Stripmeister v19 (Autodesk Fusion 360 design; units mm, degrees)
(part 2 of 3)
sketch "Sketch4" plane through (0, 0, 0) normal (0, 1, 0) x axis (1, 0, 0)
  line L1 (15.875, -65.6907) -> (15.875, -73.6282)
  line L2 (-15.875, -73.6282) -> (-15.875, -65.6907)
  line L3 (15.875, -73.6282) -> (-15.875, -73.6282)
  line L4 (15.875, -65.6907) -> (15.875, -73.6282)
  line L5 (-15.875, -65.6907) -> (15.875, -65.6907)
  line L6 (-15.875, -73.6282) -> (-15.875, -65.6907)
  line L7 (0, -73.6282) -> (0, -65.6907)
  line L8 (-5.2705, -61.7093) -> (5.2705, -61.7093)
  line L9 (-5.2705, -77.6097) -> (-5.2705, -61.7093)
  line L10 (5.2705, -77.6097) -> (-5.2705, -77.6097)
  line L11 (5.2705, -61.7093) -> (5.2705, -77.6097)
  line L12 (-5.2705, -77.6097) -> (5.2705, -61.7093)
  line L13 (5.2705, -77.6097) -> (-5.2705, -61.7093)
  line L14 (5.2705, -69.6595) -> (-5.2705, -69.6595)
  line L15 (-1.0033, -54.102) -> (1.0033, -54.102)
  line L16 (-1.0033, -85.217) -> (-1.0033, -54.102)
  line L17 (1.0033, -85.217) -> (-1.0033, -85.217)
  line L18 (1.0033, -54.102) -> (1.0033, -85.217)
  line L19 (-1.0033, -85.217) -> (1.0033, -54.102)
  line L20 (1.0033, -85.217) -> (-1.0033, -54.102)
  line L21 (1.0033, -82.3595) -> (0, -85.217)
  line L22 (-1.0033, -82.3595) -> (0, -85.217)
  point P3 (15.875, -65.6907)
  point P8 (15.875, -65.6907)
  point P5 (-15.875, -73.6282)
  point P6 (-15.875, -73.6282)
  point P10 (0, -65.6907)
  point P11 (0, -73.6282)
  point P16 (0, -69.6595)
  point P17 (-5.2705, -69.6595)
  point P18 (5.2705, -69.6595)
  point P23 (0, -69.6595)
  point P24 (0, -85.217)
  point P25 (1.0033, -82.3595)
  point P26 (0, -85.217)
  point P27 (-1.0033, -82.3595)
  point P14 (-5.2705, -77.6097)
  point P15 (5.2705, -77.6097)
  point P21 (-1.0033, -85.217)
  point P22 (1.0033, -85.217)
  point P20 (-1.0033, -54.102)
  horizontal L3
  vertical L4
  horizontal L5
  vertical L6
  coincident P3 P8
  coincident P5 P6
  midpoint L5 P10
  midpoint L3 P11
  horizontal L8
  perpendicular L8 L9
  parallel L8 L10
  parallel L9 L11
  coincident L12 P16
  coincident L13 P16
  midpoint L7 P16
  midpoint L9 P17
  midpoint L11 P18
  horizontal L15
  perpendicular L15 L16
  parallel L15 L17
  parallel L16 L18
  coincident L19 P23
  coincident L20 P23
  coincident P16 P23
  midpoint L17 P24
  coincident L18 P25
  symmetric L7 P24 P26
  symmetric L7 P25 P27
  dimension "d185" distance P14 P15 = 10.541
  dimension "d186" distance L8 L10 = 15.9004
  dimension "d187" distance P21 P22 = 2.0066
  dimension "d188" distance P20 P21 = 31.115
  dimension "d189" distance L14 P25 = 12.7
revolve "Revolve1" sketch "Sketch4" AlongAngle 360 bodies "Cutter Wheel"
work_plane "WorkPlane1" AlongDistance -6.35
sketch "Sketch5" plane through (-0.0003, -0.3714, 156.21) normal (0, 0, 1) x axis (1, 0, 0)
  circle C1 centre (0, 0) radius 14.1224
  circle C2 centre (0, 0) radius 6.35
  circle C3 centre (0, 0) radius 25.4
  point P1 (0, 0)
  point P2 (0, 0)
  point P4 (0, 0)
  coincident P1 P2
  concentric C1 C2
  coincident P1 P4
  dimension "d192" diameter C1 = 28.2448
  dimension "d193" diameter C2 = 12.7
  dimension "d194" diameter C3 = 50.8
extrude "Extrude9" new body sketch "Sketch5" profile of C1 C2 along normal blind 34.925
extrude "Extrude10" sketch "Sketch5" profile of C2 to an object
extrude "Extrude11" add sketch "Sketch5" profile of C1 C3 to an object from offset 14.2875 (= "( 9 / 16 ) * 1 in")
sketch "Sketch6" plane through (0, 0, 191.135) normal (0, 0, 1) x axis (-1, 0, 0)
  line L1 (0.0003, 25.7714) -> (0.0003, 0.3714)
  circle C1 centre (0.0003, 0.3714) radius 25.4
  circle C2 centre (0.0003, 19.4214) radius 6.35
  circle C3 centre (-14.8935, 12.2489) radius 6.35
  circle C4 centre (-18.572, -3.8676) radius 6.35
  circle C5 centre (-8.2651, -16.792) radius 6.35
  circle C6 centre (8.2658, -16.792) radius 6.35
  circle C7 centre (18.5727, -3.8676) radius 6.35
  circle C8 centre (14.8942, 12.2489) radius 6.35
  circle C9 centre (11.6309, 24.5225) radius 6.35
  circle C10 centre (26.1339, 6.3362) radius 6.35
  circle C11 centre (20.9578, -16.3416) radius 6.35
  circle C12 centre (0.0003, -26.4342) radius 6.35
  circle C13 centre (-20.9571, -16.3416) radius 6.35
  circle C14 centre (-26.1332, 6.3362) radius 6.35
  circle C15 centre (-11.6302, 24.5225) radius 6.35
  point P2 (0.0003, 0.3714)
  point P3 (0.0003, 0.3714)
  point P4 (0.0003, 25.7714)
  point P5 (0.0003, 19.4214)
  coincident P2 P3
  coincident C1 P4
  vertical L1
  coincident L1 P5
  tangent C1 C2
  tangent C2 C9
  tangent C8 C9
  tangent C2 C15
  tangent C3 C15
  tangent C3 C14
  tangent C4 C14
  tangent C4 C13
  tangent C5 C13
  tangent C5 C12
  tangent C6 C12
  tangent C6 C11
  tangent C7 C11
  tangent C7 C10
  tangent C8 C10
  dimension "d203" diameter C2 = 12.7
  dimension "d207" diameter C9 = 12.7
  dimension "d208" diameter C10 = 12.7
  dimension "d209" diameter C11 = 12.7
  dimension "d210" diameter C12 = 12.7
  dimension "d211" diameter C13 = 12.7
  dimension "d212" diameter C14 = 12.7
  dimension "d213" diameter C15 = 12.7
  dimension "d205" C-Pattern1-Angle = 360
extrude "Extrude12" cut sketch "Sketch6" profile of C1 C2 C3 C4 C5 C6 C7 C8 C9 C10 C11 C12 C13 C14 C15 against normal blind 20.6502
sketch "Sketch7" plane through (0, 0, 0) normal (0, 1, 0) x axis (1, 0, 0)
  line L1 (-21.2442, -170.4975) -> (-14.1227, -170.4975)
  line L2 (-13.2626, -191.135) -> (-21.2442, -191.135)
  line L3 (-22.3533, -170.4975) -> (-21.2442, -170.4975)
  line L4 (-21.2442, -191.135) -> (-22.3533, -191.135)
  line L5 (-24.9227, -170.4975) -> (-22.3533, -170.4975)
  line L6 (-22.3533, -191.135) -> (-24.9227, -191.135)
  line L7 (-5.8156, -191.135) -> (-13.2626, -191.135)
  line L8 (14.1221, -170.4975) -> (21.2435, -170.4975)
  line L9 (21.2435, -191.135) -> (13.2619, -191.135)
  line L10 (13.2619, -191.135) -> (5.8149, -191.135)
  line L11 (5.8149, -191.135) -> (-5.8156, -191.135)
  line L12 (22.3526, -170.4975) -> (24.922, -170.4975)
  line L13 (24.922, -191.135) -> (22.3526, -191.135)
  line L14 (21.2435, -170.4975) -> (22.3526, -170.4975)
  line L15 (22.3526, -191.135) -> (21.2435, -191.135)
  line L16 (14.1221, -156.21) -> (-14.1227, -156.21)
  line L17 (-24.9227, -170.4975) -> (-24.9227, -191.135)
  line L18 (24.922, -170.4975) -> (24.922, -191.135)
  line L19 (-14.1227, -170.4975) -> (-14.1227, -156.21)
  line L20 (14.1221, -170.4975) -> (14.1221, -156.21)
  line L21 (-24.9227, -183.1975) -> (-24.9227, -170.4975)
  line L22 (24.922, -183.1975) -> (24.922, -170.4975)
  line L23 (24.922, -170.4975) -> (-24.9227, -170.4975)
  line L24 (-0.0004, -191.135) -> (-0.0003, -170.4975)
  line L25 (50.7996, -191.135) -> (-0.0004, -191.135)
  line L26 (50.7996, -170.4975) -> (50.7996, -191.135)
  line L27 (-0.0004, -170.4975) -> (50.7996, -170.4975)
  line L28 (-0.0004, -191.135) -> (-0.0004, -170.4975)
  line L29 (35.082, -191.135) -> (24.922, -191.135)
  line L30 (35.082, -183.1975) -> (35.082, -191.135)
  line L31 (24.922, -183.1975) -> (35.082, -183.1975)
  line L32 (24.922, -191.135) -> (24.922, -183.1975)
  arc A1 centre (-0.0003, -148.0403) radius 43.0947 clockwise from (35.082, -173.0679) to (-24.9227, -183.1975)
  point P8 (-24.9227, -170.4975)
  point P22 (-24.9227, -170.4975)
  point P23 (-24.9227, -183.1975)
  point P16 (24.922, -170.4975)
  point P24 (24.922, -170.4975)
  point P27 (24.922, -170.4975)
  point P28 (-0.0003, -170.4975)
  point P29 (-0.0004, -191.135)
  point P19 (24.922, -191.135)
  point P33 (24.922, -191.135)
  point P25 (24.922, -183.1975)
  point P30 (50.7996, -191.135)
  point P34 (35.082, -191.135)
  coincident P8 P22
  coincident L17 P23
  coincident P16 P24
  perpendicular L12 L22
  coincident P16 P27
  midpoint L23 P28
  midpoint L11 P29
  horizontal L25
  vertical L26
  horizontal L27
  vertical L28
  collinear L23 L27
  horizontal L29
  vertical L30
  horizontal L31
  vertical L32
  coincident P19 P33
  coincident A1 P29
  coincident P25 A1
  dimension "d216" distance P22 P23 = 12.7
  dimension "d217" distance P24 P25 = 12.7
  dimension "d219" distance P29 P30 = 50.8
  dimension "d220" distance P33 P34 = 10.16
work_plane "WorkPlane2" RotateAngle 0
work_plane "WorkPlane3" RotateAngle 0
work_plane "WorkPlane4"
sketch "Sketch8" plane through (-0.0003, -0.3714, 160.8667) normal (0, -1, 0) x axis (1, 0, 0)
  line L1 (24.9224, 30.2683) -> (24.9224, 22.3308)
  line L2 (50.8, 30.2683) -> (0, 30.2683)
  line L3 (0, 30.2683) -> (0, 9.6308)
  arc A1 centre (0, -12.8264) radius 43.0947 clockwise from (-24.9224, 22.3308) to (35.0824, 12.2012)
revolve "Revolve3" sketch "Sketch7" AlongAngle 360
delete_face "DeleteFace1"
delete_face "DeleteFace2"
delete_face "DeleteFace3"
delete_face "DeleteFace4"
delete_face "DeleteFace5"
delete_face "DeleteFace6"
delete_face "DeleteFace7"
sketch "Sketch2" plane through (-19.05, 0, 0) normal (1, 0, 0) x axis (0, 1, 0)
  line L1 (-31.75, 15.748) -> (-31.75, 93.472)
  line L2 (-20.574, 93.472) -> (-20.574, 15.748)
  line L3 (-26.162, 26.035) -> (-26.162, 10.16)
  line L4 (-26.162, 85.5663) -> (-26.162, 99.06)
  line L5 (-28.9401, 28.8131) -> (-28.9401, 82.7881)
  line L6 (-23.3839, 82.7881) -> (-23.3839, 28.8131)
  line L7 (-26.162, 26.035) -> (-26.162, 85.5663)
  arc A1 centre (-26.162, 93.472) radius 5.588 clockwise from (-31.75, 93.472) to (-20.574, 93.472)
  arc A2 centre (-26.162, 15.748) radius 5.588 clockwise from (-20.574, 15.748) to (-31.75, 15.748)
  arc A3 centre (-26.162, 28.8131) radius 2.7781 clockwise from (-23.3839, 28.8131) to (-28.9401, 28.8131)
  arc A4 centre (-26.162, 82.7881) radius 2.7781 clockwise from (-28.9401, 82.7881) to (-23.3839, 82.7881)
  point P8 (-26.162, 10.16)
  point P10 (-26.162, 99.06)
  point P11 (-26.162, 85.5663)
  point P9 (-26.162, 26.035)
  midpoint A2 P8
  vertical L3
  midpoint A1 P10
  vertical L4
  tangent L5 A3
  tangent A3 L6
  parallel L5 L6
  tangent L6 A4
  tangent L5 A4
  midpoint P11 A4
  midpoint P9 A3
  dimension "d224" distance P8 P9 = 15.875 (= "( 5 / 8 ) * 1 in")
  dimension "d225" distance P10 P11 = 13.4938 (= "( 17 / 32 ) * 1 in")
  dimension "d226" diameter A3 = 5.5563 (= "( 7 / 32 ) * 1 in")
extrude "Extrude2" cut sketch "Sketch2" profile of L5 A3 L6 A4 against normal blind 9.525
sketch "Sketch3" plane through (0, 0, 127) normal (0, 0, 1) x axis (-1, 0, 0)
  line L1 (19.05, -7.3041) -> (19.05, 7.3041)
  line L2 (15.875, -7.3041) -> (19.05, -7.3041)
  line L3 (15.875, -38.1) -> (15.875, -7.3041)
  line L4 (28.575, -38.1) -> (15.875, -38.1)
  line L5 (28.575, 38.1) -> (28.575, -38.1)
  line L6 (15.875, 38.1) -> (28.575, 38.1)
  line L7 (15.875, 7.3041) -> (15.875, 38.1)
  line L8 (19.05, 7.3041) -> (15.875, 7.3041)
  line L9 (15.875, 36.9341) -> (19.6088, 38.1)
  circle C1 centre (22.225, 25.4) radius 5.5245
  circle C2 centre (22.225, -25.4) radius 5.5245
  point P12 (19.6088, 38.1)
  point P13 (15.875, 36.9341)
  point P7 (28.575, 38.1)
  coincident L6 P12
  coincident L7 P13
  dimension "d229" distance P12 P13 = 3.9116
  dimension "d230" distance P7 P12 = 8.9662
extrude "Extrude3" cut sketch "Sketch3" profile of L6 L7 L9 blind -25.4 from offset -67.6783
sketch "Sketch4" plane through (9.098, -29.136, 0) normal (0.2981, -0.9545, 0) x axis (0.9545, 0.2981, 0)
  line L1 (-30.0738, 59.3217) -> (-26.1622, 59.3217)
  line L2 (-30.0738, 33.9217) -> (-30.0738, 59.3217)
  line L3 (-26.1622, 33.9217) -> (-30.0738, 33.9217)
  line L4 (-26.1622, 59.3217) -> (-26.1622, 33.9217)
  line L5 (-29.1622, 46.9967) -> (-26.1622, 46.9967)
  line L6 (-29.1622, 46.2467) -> (-29.1622, 46.9967)
  line L7 (-26.1622, 46.2467) -> (-29.1622, 46.2467)
  line L8 (-26.1622, 46.9967) -> (-26.1622, 46.2467)
  line L9 (-26.1622, 36.0867) -> (-29.1622, 36.0867)
  line L10 (-29.1622, 36.0867) -> (-29.1622, 36.8367)
  line L11 (-29.1622, 36.8367) -> (-26.1622, 36.8367)
  line L12 (-26.1622, 38.1187) -> (-29.1622, 38.1187)
  line L13 (-29.1622, 38.1187) -> (-29.1622, 38.8687)
  line L14 (-29.1622, 38.8687) -> (-26.1622, 38.8687)
  line L15 (-26.1622, 40.1507) -> (-29.1622, 40.1507)
  line L16 (-29.1622, 40.1507) -> (-29.1622, 40.9007)
  line L17 (-29.1622, 40.9007) -> (-26.1622, 40.9007)
  line L18 (-26.1622, 42.1827) -> (-29.1622, 42.1827)
  line L19 (-29.1622, 42.1827) -> (-29.1622, 42.9327)
  line L20 (-29.1622, 42.9327) -> (-26.1622, 42.9327)
  line L21 (-26.1622, 44.2147) -> (-29.1622, 44.2147)
  line L22 (-29.1622, 44.2147) -> (-29.1622, 44.9647)
  line L23 (-29.1622, 44.9647) -> (-26.1622, 44.9647)
  line L24 (-26.1622, 48.2787) -> (-29.1622, 48.2787)
  line L25 (-29.1622, 48.2787) -> (-29.1622, 49.0287)
  line L26 (-29.1622, 49.0287) -> (-26.1622, 49.0287)
  line L27 (-26.1622, 50.3107) -> (-29.1622, 50.3107)
  line L28 (-29.1622, 50.3107) -> (-29.1622, 51.0607)
  line L29 (-29.1622, 51.0607) -> (-26.1622, 51.0607)
  line L30 (-26.1622, 52.3427) -> (-29.1622, 52.3427)
  line L31 (-29.1622, 52.3427) -> (-29.1622, 53.0927)
  line L32 (-29.1622, 53.0927) -> (-26.1622, 53.0927)
  line L33 (-26.1622, 54.3747) -> (-29.1622, 54.3747)
  line L34 (-29.1622, 54.3747) -> (-29.1622, 55.1247)
  line L35 (-29.1622, 55.1247) -> (-26.1622, 55.1247)
  line L36 (-26.1622, 56.4067) -> (-29.1622, 56.4067)
  line L37 (-29.1622, 56.4067) -> (-29.1622, 57.1567)
  line L38 (-29.1622, 57.1567) -> (-26.1622, 57.1567)
  line L39 (-26.1622, 57.1567) -> (-29.1622, 57.1567)
  line L40 (-29.1622, 57.1567) -> (-27.6622, 57.1567)
  line L41 (-28.4122, 36.0867) -> (-28.4122, 57.1567)
  point P6 (-26.1622, 46.9967)
  point P50 (-27.6622, 57.1567)
  point P51 (-28.4122, 57.1567)
  point P52 (-28.4122, 36.0867)
  point P7 (-29.1622, 46.9967)
  point P9 (-26.1622, 46.2467)
  horizontal L5
  vertical L6
  horizontal L7
  vertical L8
  coincident L4 P6
  midpoint L4 L8
  midpoint L38 P50
  midpoint L40 P51
  coincident L9 P52
  perpendicular L9 L41
  dimension "d234" distance P6 P7 = 3
  dimension "d235" distance P6 P9 = 0.75
  dimension "d238" R-Pattern1-uDistance = 0
  dimension "d239" R-Pattern1-vDistance = 10.16
extrude "Extrude4" cut sketch "Sketch4" profile of L4 L5 L6 L7 L8 L9 L10 L11 L12 L14 L15 L17 L18 L20 L21 L23 L24 L26 L27 L29 L30 L32 L33 L35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 against normal blind 0.25
extrude "Extrude5" cut of existing geometry blind -1.524
sketch "Sketch1" plane through (-15.875, 0, 0) normal (1, 0, 0) x axis (0, 1, 0)
  line L1 (-36.9341, 38.1187) -> (-36.6722, 38.1187)
  line L2 (-36.9341, 36.8367) -> (-36.9341, 38.1187)
  line L3 (-36.6722, 36.8367) -> (-36.9341, 36.8367)
  line L4 (-36.6722, 36.0867) -> (-36.6722, 36.8367)
  line L5 (-36.9341, 36.0867) -> (-36.6722, 36.0867)
  line L6 (-36.9341, 33.9217) -> (-36.9341, 36.0867)
  line L7 (-38.1, 33.9217) -> (-36.9341, 33.9217)
  line L8 (-38.1, 0) -> (-38.1, 33.9217)
  line L9 (38.1, 0) -> (-38.1, 0)
  line L10 (38.1, 127) -> (38.1, 0)
  line L11 (7.3041, 127) -> (38.1, 127)
  line L12 (5.588, 116.84) -> (6.0357, 125.7934)
  line L13 (5.588, 58.2803) -> (5.588, 116.84)
  line L14 (-5.588, 116.84) -> (-5.588, 58.2803)
  line L15 (-6.0357, 125.7934) -> (-5.588, 116.84)
  line L16 (-38.1, 127) -> (-7.3041, 127)
  line L17 (-38.1, 59.3217) -> (-38.1, 127)
  line L18 (-36.9341, 59.3217) -> (-38.1, 59.3217)
  line L19 (-36.9341, 57.1567) -> (-36.9341, 59.3217)
  line L20 (-36.6722, 57.1567) -> (-36.9341, 57.1567)
  line L21 (-36.6722, 56.4067) -> (-36.6722, 57.1567)
  line L22 (-36.9341, 56.4067) -> (-36.6722, 56.4067)
  line L23 (-36.9341, 55.1247) -> (-36.9341, 56.4067)
  line L24 (-36.6722, 55.1247) -> (-36.9341, 55.1247)
  line L25 (-36.6722, 54.3747) -> (-36.6722, 55.1247)
  line L26 (-36.9341, 54.3747) -> (-36.6722, 54.3747)
  line L27 (-36.9341, 53.0927) -> (-36.9341, 54.3747)
  line L28 (-36.6722, 53.0927) -> (-36.9341, 53.0927)
  line L29 (-36.6722, 52.3427) -> (-36.6722, 53.0927)
  line L30 (-36.9341, 52.3427) -> (-36.6722, 52.3427)
  line L31 (-36.9341, 51.0607) -> (-36.9341, 52.3427)
  line L32 (-36.6722, 51.0607) -> (-36.9341, 51.0607)
  line L33 (-36.6722, 50.3107) -> (-36.6722, 51.0607)
  line L34 (-36.9341, 50.3107) -> (-36.6722, 50.3107)
  line L35 (-36.9341, 49.0287) -> (-36.9341, 50.3107)
  line L36 (-36.6722, 49.0287) -> (-36.9341, 49.0287)
  line L37 (-36.6722, 48.2787) -> (-36.6722, 49.0287)
  line L38 (-36.9341, 48.2787) -> (-36.6722, 48.2787)
  line L39 (-36.9341, 46.9967) -> (-36.9341, 48.2787)
  line L40 (-36.6722, 46.9967) -> (-36.9341, 46.9967)
  line L41 (-36.6722, 46.2467) -> (-36.6722, 46.9967)
  line L42 (-36.9341, 46.2467) -> (-36.6722, 46.2467)
  line L43 (-36.9341, 44.9647) -> (-36.9341, 46.2467)
  line L44 (-36.6722, 44.9647) -> (-36.9341, 44.9647)
  line L45 (-36.6722, 44.2147) -> (-36.6722, 44.9647)
  line L46 (-36.9341, 44.2147) -> (-36.6722, 44.2147)
  line L47 (-36.9341, 42.9327) -> (-36.9341, 44.2147)
  line L48 (-36.6722, 42.9327) -> (-36.9341, 42.9327)
  line L49 (-36.6722, 42.1827) -> (-36.6722, 42.9327)
  line L50 (-36.9341, 42.1827) -> (-36.6722, 42.1827)
  line L51 (-36.9341, 40.9007) -> (-36.9341, 42.1827)
  line L52 (-36.6722, 40.9007) -> (-36.9341, 40.9007)
  line L53 (-36.6722, 40.1507) -> (-36.6722, 40.9007)
  line L54 (-36.9341, 40.1507) -> (-36.6722, 40.1507)
  line L55 (-36.9341, 38.8687) -> (-36.9341, 40.1507)
  line L56 (-36.6722, 38.8687) -> (-36.9341, 38.8687)
  line L57 (-36.6722, 38.1187) -> (-36.6722, 38.8687)
  line L58 (-20.574, 15.748) -> (-20.574, 93.472)
  line L59 (-31.75, 93.472) -> (-31.75, 15.748)
  line L60 (-11.475, 89.1) -> (-16.725, 89.1)
  line L61 (-16.725, 88.35) -> (-11.475, 88.35)
  line L62 (-11.475, 97.5667) -> (-16.725, 97.5667)
  line L63 (-16.725, 96.8167) -> (-11.475, 96.8167)
  line L64 (-11.475, 106.0333) -> (-16.725, 106.0333)
  line L65 (-16.725, 105.2833) -> (-11.475, 105.2833)
  line L66 (-16.725, 113.75) -> (-11.475, 113.75)
  line L67 (-11.475, 114.5) -> (-16.725, 114.5)
  line L68 (-11.475, 108.15) -> (-16.725, 108.15)
  line L69 (-16.725, 107.4) -> (-11.475, 107.4)
  line L70 (-11.475, 99.6833) -> (-16.725, 99.6833)
  line L71 (-16.725, 98.9333) -> (-11.475, 98.9333)
  line L72 (-11.475, 91.2167) -> (-16.725, 91.2167)
  line L73 (-16.725, 90.4667) -> (-11.475, 90.4667)
  line L74 (-11.475, 95.45) -> (-16.725, 95.45)
  line L75 (-16.725, 94.7) -> (-11.475, 94.7)
  line L76 (-11.475, 103.9167) -> (-16.725, 103.9167)
  line L77 (-16.725, 103.1667) -> (-11.475, 103.1667)
  line L78 (-11.475, 112.3833) -> (-16.725, 112.3833)
  line L79 (-16.725, 111.6333) -> (-11.475, 111.6333)
  line L80 (-11.475, 110.2667) -> (-16.725, 110.2667)
  line L81 (-16.725, 109.5167) -> (-11.475, 109.5167)
  line L82 (-11.475, 101.8) -> (-16.725, 101.8)
  line L83 (-16.725, 101.05) -> (-11.475, 101.05)
  line L84 (-11.475, 93.3333) -> (-16.725, 93.3333)
  line L85 (-16.725, 92.5833) -> (-11.475, 92.5833)
  line L86 (-28.9401, 82.7881) -> (-28.9401, 28.8131)
  line L87 (-23.3839, 28.8131) -> (-23.3839, 82.7881)
  line L88 (-31.75, 15.748) -> (-31.75, 93.472)
  line L89 (-20.574, 93.472) -> (-20.574, 15.748)
  line L90 (-16.637, 105.41) -> (-35.687, 105.41)
  line L91 (-16.637, 41.91) -> (-16.637, 105.41)
  line L92 (-35.687, 41.91) -> (-16.637, 41.91)
  line L93 (-35.687, 105.41) -> (-35.687, 41.91)
  line L94 (-26.162, 105.41) -> (-26.162, 82.7881)
  line L95 (-26.162, 61.8998) -> (-26.162, 99.06)
  line L96 (-38.1, 93.472) -> (-38.1, 15.748)
  line L97 (-14.224, 15.748) -> (-14.224, 93.472)
  line L98 (-28.9401, 28.8131) -> (-28.9401, 82.7881)
  line L99 (-23.3839, 82.7881) -> (-23.3839, 28.8131)
  line L100 (-38.1, 0) -> (38.1, 0)
  line L101 (-38.1, 127) -> (-38.1, 0)
  line L102 (38.1, 127) -> (-38.1, 127)
  line L103 (38.1, 0) -> (38.1, 127)
  arc A1 centre (7.3041, 125.73) radius 1.27 clockwise from (6.0357, 125.7934) to (7.3041, 127)
  arc A2 centre (0, 58.2803) radius 5.588 clockwise from (5.588, 58.2803) to (-5.588, 58.2803)
  arc A3 centre (-7.3041, 125.73) radius 1.27 clockwise from (-7.3041, 127) to (-6.0357, 125.7934)
  arc A4 centre (-26.162, 15.748) radius 5.588 clockwise from (-20.574, 15.748) to (-31.75, 15.748)
  arc A5 centre (-26.162, 93.472) radius 5.588 clockwise from (-31.75, 93.472) to (-20.574, 93.472)
  circle C1 centre (0, 38.1) radius 11.049
  arc A6 centre (-11.475, 88.725) radius 0.375 clockwise from (-11.475, 89.1) to (-11.475, 88.35)
  arc A7 centre (-16.725, 88.725) radius 0.375 clockwise from (-16.725, 88.35) to (-16.725, 89.1)
  arc A8 centre (-11.475, 97.1917) radius 0.375 clockwise from (-11.475, 97.5667) to (-11.475, 96.8167)
  arc A9 centre (-16.725, 97.1917) radius 0.375 clockwise from (-16.725, 96.8167) to (-16.725, 97.5667)
  arc A10 centre (-11.475, 105.6583) radius 0.375 clockwise from (-11.475, 106.0333) to (-11.475, 105.2833)
  arc A11 centre (-16.725, 105.6583) radius 0.375 clockwise from (-16.725, 105.2833) to (-16.725, 106.0333)
  arc A12 centre (-16.725, 114.125) radius 0.375 clockwise from (-16.725, 113.75) to (-16.725, 114.5)
  arc A13 centre (-11.475, 114.125) radius 0.375 clockwise from (-11.475, 114.5) to (-11.475, 113.75)
  arc A14 centre (-11.475, 107.775) radius 0.375 clockwise from (-11.475, 108.15) to (-11.475, 107.4)
  arc A15 centre (-16.725, 107.775) radius 0.375 clockwise from (-16.725, 107.4) to (-16.725, 108.15)
  arc A16 centre (-11.475, 99.3083) radius 0.375 clockwise from (-11.475, 99.6833) to (-11.475, 98.9333)
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  point P153 (-26.162, 82.7881)
  point P166 (-26.162, 82.7881)
  point P167 (-26.162, 105.41)
  point P162 (-35.687, 105.41)
  point P163 (-16.637, 105.41)
  point P165 (-35.687, 41.91)
  point P168 (-26.162, 99.06)
  point P169 (-26.162, 61.8998)
  horizontal L90
  vertical L91
  horizontal L92
  vertical L93
  coincident P153 P166
  midpoint L90 P167
  parallel L94 L95
  dimension "d245" distance P162 P163 = 19.05
  dimension "d246" distance P162 P165 = 63.5
  dimension "d247" distance P168 P169 = 37.1602
  dimension "d248" = 6.35
extrude "Extrude1" new body sketch "Sketch1" along normal blind 31.75
extrude "Extrude2" add sketch "Sketch1" against normal blind 2.794
extrude "Extrude3" of existing geometry blind -2.794
sketch "Sketch2" plane through (15.875, 0, 0) normal (1, 0, 0) x axis (0, 1, 0)
  line L1 (-20.574, 67.4878) -> (-20.574, 93.472)
  line L2 (-31.75, 93.472) -> (-31.75, 67.4878)
  line L3 (-16.637, 41.91) -> (-35.687, 41.91)
  line L4 (-16.637, 88.35) -> (-16.637, 41.91)
  line L5 (-16.725, 88.35) -> (-16.637, 88.35)
  line L6 (-16.637, 89.1) -> (-16.725, 89.1)
  line L7 (-16.637, 92.5833) -> (-16.637, 89.1)
  line L8 (-16.725, 92.5833) -> (-16.637, 92.5833)
  line L9 (-16.637, 93.3333) -> (-16.725, 93.3333)
  line L10 (-16.637, 94.7) -> (-16.637, 93.3333)
  line L11 (-16.725, 94.7) -> (-16.637, 94.7)
  line L12 (-16.637, 95.45) -> (-16.725, 95.45)
  line L13 (-16.637, 96.8167) -> (-16.637, 95.45)
  line L14 (-16.725, 96.8167) -> (-16.637, 96.8167)
  line L15 (-16.637, 97.5667) -> (-16.725, 97.5667)
  line L16 (-16.637, 98.9333) -> (-16.637, 97.5667)
  line L17 (-16.725, 98.9333) -> (-16.637, 98.9333)
  line L18 (-16.637, 99.6833) -> (-16.725, 99.6833)
  line L19 (-16.637, 101.05) -> (-16.637, 99.6833)
  line L20 (-16.725, 101.05) -> (-16.637, 101.05)
  line L21 (-16.637, 101.8) -> (-16.725, 101.8)
  line L22 (-16.637, 103.1667) -> (-16.637, 101.8)
  line L23 (-16.725, 103.1667) -> (-16.637, 103.1667)
  line L24 (-16.637, 103.9167) -> (-16.725, 103.9167)
  line L25 (-16.637, 105.2833) -> (-16.637, 103.9167)
  line L26 (-16.725, 105.2833) -> (-16.637, 105.2833)
  line L27 (-35.687, 105.41) -> (-17.006, 105.41)
  line L28 (-35.687, 41.91) -> (-35.687, 105.41)
  line L29 (-19.177, 41.91) -> (-16.637, 41.91)
  line L30 (-19.177, 105.41) -> (-19.177, 41.91)
  line L31 (-16.637, 105.41) -> (-19.177, 105.41)
  line L32 (-16.637, 41.91) -> (-16.637, 105.41)
  arc A1 centre (-26.162, 67.4878) radius 5.588 clockwise from (-20.574, 67.4878) to (-31.75, 67.4878)
  arc A2 centre (-26.162, 93.472) radius 5.588 clockwise from (-31.75, 93.472) to (-20.574, 93.472)
  arc A3 centre (-16.725, 88.725) radius 0.375 clockwise from (-16.725, 88.35) to (-16.725, 89.1)
  arc A4 centre (-16.725, 92.9583) radius 0.375 clockwise from (-16.725, 92.5833) to (-16.725, 93.3333)
  arc A5 centre (-16.725, 95.075) radius 0.375 clockwise from (-16.725, 94.7) to (-16.725, 95.45)
  arc A6 centre (-16.725, 97.1917) radius 0.375 clockwise from (-16.725, 96.8167) to (-16.725, 97.5667)
  arc A7 centre (-16.725, 99.3083) radius 0.375 clockwise from (-16.725, 98.9333) to (-16.725, 99.6833)
  arc A8 centre (-16.725, 101.425) radius 0.375 clockwise from (-16.725, 101.05) to (-16.725, 101.8)
  arc A9 centre (-16.725, 103.5417) radius 0.375 clockwise from (-16.725, 103.1667) to (-16.725, 103.9167)
  arc A10 centre (-16.725, 105.6583) radius 0.375 clockwise from (-16.725, 105.2833) to (-17.006, 105.41)
  point P53 (-19.177, 105.41)
  point P50 (-16.637, 41.91)
  point P51 (-16.637, 41.91)
  horizontal L29
  vertical L30
  horizontal L31
  vertical L32
  coincident L27 P53
  coincident P50 P51
  dimension "d256" distance L30 L32 = 2.54
extrude "Extrude4" add sketch "Sketch2" profile of L3 L4 L5 A3 L6 L7 L8 A4 L9 L10 L11 A5 L12 L13 L14 A6 L15 L16 L17 A7 L18 L19 L20 A8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 against normal blind 31.75
move "Move1"
sketch "Sketch3" plane through (-18.669, 0, 0) normal (-1, 0, 0) x axis (0, -1, 0)
  line L1 (31.75, 80.772) -> (31.75, 54.7878)
  line L2 (20.574, 54.7878) -> (20.574, 80.772)
  line L3 (26.162, 86.36) -> (26.162, 49.1998)
  arc A1 centre (26.162, 80.772) radius 5.588 clockwise from (20.574, 80.772) to (31.75, 80.772)
  arc A2 centre (26.162, 54.7878) radius 5.588 clockwise from (31.75, 54.7878) to (20.574, 54.7878)
  circle C1 centre (26.162, 67.7799) radius 2.3813
  point P8 (26.162, 49.1998)
  point P9 (26.162, 86.36)
  point P10 (26.162, 67.7799)
  midpoint A2 P8
  midpoint A1 P9
  midpoint L3 P10
  dimension "d259" diameter C1 = 4.7625 (= "( 3 / 16 ) * 1 in")
extrude "Extrude5" cut sketch "Sketch3" profile of C1 against normal blind 12.065
thread "Thread1"
delete_face "DeleteFace1"
sketch "Sketch4" plane through (0, 0, 92.71) normal (0, 0, 1) x axis (-1, 0, 0)
  line L1 (15.875, 35.687) -> (15.875, 16.637)
  line L2 (-15.875, 35.687) -> (15.875, 35.687)
  line L3 (-15.875, 16.637) -> (-15.875, 35.687)
  line L4 (15.875, 16.637) -> (-15.875, 16.637)
  line L5 (-15.875, 16.1282) -> (-15.875, 16.637)
  line L6 (0, 16.129) -> (0, 16.637)
  line L7 (-1.1753, 12.9707) -> (0, 16.129)
  line L8 (-3.175, 12.065) -> (-3.175, 16.637)
  line L9 (15.875, 15.621) -> (15.875, 16.637)
  line L10 (1.1753, 12.9707) -> (0, 16.129)
  arc A1 centre (-15.6591, -8.0645) radius 23.6865 clockwise from (-15.3731, 15.6203) to (-3.3928, 12.1985)
  arc A2 centre (-2.6036, 13.5022) radius 1.524 clockwise from (-1.1753, 12.9707) to (-3.3928, 12.1985)
  arc A3 centre (15.6591, -8.0645) radius 23.6865 clockwise from (3.3928, 12.1985) to (15.875, 15.621)
  arc A4 centre (2.6036, 13.5022) radius 1.524 clockwise from (3.3928, 12.1985) to (1.1753, 12.9707)
  arc A5 centre (-15.367, 16.1282) radius 0.508 clockwise from (-15.3731, 15.6203) to (-15.875, 16.1282)
  arc A6 centre (15.367, 16.1282) radius 0.508 clockwise from (15.875, 16.1282) to (15.3731, 15.6203)
  point P5 (-15.875, 16.637)
  point P6 (-15.875, 16.637)
  point P8 (0, 16.637)
  point P10 (-3.175, 16.637)
  point P11 (-3.175, 12.065)
  point P16 (15.875, 16.637)
  point P7 (-15.875, 15.621)
  point P17 (15.875, 15.621)
  point P9 (0, 16.129)
  point P22 (0, 16.129)
  point P13 (-1.1753, 12.9707)
  point P21 (1.1753, 12.9707)
  point P14 (-3.3928, 12.1985)
  point P19 (3.3928, 12.1985)
  point P23 (-15.875, 16.1282)
  point P27 (15.875, 16.1282)
  point P24 (-15.3731, 15.6203)
  point P28 (15.3731, 15.6203)
  coincident P5 P6
  perpendicular L4 L5
  midpoint L4 P8
  perpendicular L4 L6
  coincident L4 P10
  perpendicular L4 L8
  coincident P11 A1
  tangent A1 A2
  tangent L7 A2
  symmetric P6 L6 P16
  symmetric P7 L6 P17
  symmetric P9 L6 P22
  symmetric L6 A1 A3
  symmetric L6 P13 P21
  symmetric L6 P14 P19
  symmetric L6 A2 A4
  coincident P7 L5
  tangent L5 A5
  tangent A1 A5
  symmetric L6 P23 P27
  symmetric L6 P24 P28
  symmetric L6 A5 A6
  dimension "d262" distance P6 P7 = 1.016
  dimension "d263" distance P8 P9 = 0.508
  dimension "d265" distance P10 P11 = 4.572
  dimension "d266" distance P6 L8 = 12.7
  dimension "d268" radius A2 = 1.524
  dimension "d269" distance P9 P13 = 3.1583
  dimension "d270" radius A1 = 23.6865
  dimension "d271" radius A5 = 0.508
extrude "Extrude6" sketch "Sketch4" profile of L4 L5 L6 L7 A1 A2 L9 A3 A4 L10 A5 A6 blind 39.37
fillet "Fillet1" radius 0.254
sketch "Sketch5" plane through (0, 0, 29.21) normal (0, 0, -1) x axis (1, 0, 0)
  line L1 (15.875, 35.687) -> (15.875, 16.1282)
  line L2 (-15.875, 35.687) -> (15.875, 35.687)
  line L3 (-15.875, 16.1282) -> (-15.875, 35.687)
  line L4 (-0.2381, 15.4893) -> (-1.1753, 12.9707)
  line L5 (1.1753, 12.9707) -> (0.2381, 15.4893)
  line L6 (3.81, 35.687) -> (-3.81, 35.687)
  line L7 (3.81, 11.6459) -> (3.81, 35.687)
  line L8 (-3.81, 11.6459) -> (3.81, 11.6459)
  line L9 (-3.81, 35.687) -> (-3.81, 11.6459)
  arc A1 centre (-15.367, 16.1282) radius 0.508 clockwise from (-15.3731, 15.6203) to (-15.875, 16.1282)
  arc A2 centre (-15.6591, -8.0645) radius 23.6865 clockwise from (-15.3731, 15.6203) to (-3.3928, 12.1985)
  arc A3 centre (-2.6036, 13.5022) radius 1.524 clockwise from (-1.1753, 12.9707) to (-3.3928, 12.1985)
  arc A4 centre (0, 15.4007) radius 0.254 clockwise from (-0.2381, 15.4893) to (0.2381, 15.4893)
  arc A5 centre (2.6036, 13.5022) radius 1.524 clockwise from (3.3928, 12.1985) to (1.1753, 12.9707)
  arc A6 centre (15.6591, -8.0645) radius 23.6865 clockwise from (3.3928, 12.1985) to (15.3731, 15.6203)
  arc A7 centre (15.367, 16.1282) radius 0.508 clockwise from (15.875, 16.1282) to (15.3731, 15.6203)
  point P21 (-3.81, 35.687)
  point P22 (3.81, 35.687)
  point P24 (-3.81, 11.6459)
  horizontal L6
  vertical L7
  horizontal L8
  vertical L9
  coincident L2 P21
  midpoint L2 L6
  dimension "d277" distance P21 P22 = 7.62
  dimension "d278" distance P21 P24 = 24.0411
sketch "Sketch6" plane through (0, -35.687, 0) normal (0, -1, 0) x axis (1, 0, 0)
  line L1 (-15.875, 29.21) -> (-15.875, 92.71)
  line L2 (15.875, 29.21) -> (-15.875, 29.21)
  line L3 (15.875, 92.71) -> (15.875, 29.21)
  line L4 (-15.875, 92.71) -> (15.875, 92.71)
  line L5 (0, 29.21) -> (0, 92.71)
  line L6 (15.875, 31.1404) -> (-15.875, 31.1404)
  line L7 (15.875, 39.37) -> (-15.875, 39.37)
  line L8 (15.875, 51.816) -> (-15.875, 51.816)
  line L9 (-15.875, 29.21) -> (15.875, 29.21)
  line L10 (15.875, 88.773) -> (-15.875, 88.773)
  line L11 (-6.223, 51.816) -> (-6.223, 88.773)
  line L12 (3.5306, 51.816) -> (3.5306, 88.3968)
  line L13 (3.5306, 64.4652) -> (-6.223, 64.4652)
  line L14 (-3.2757, 53.8613) -> (-5.8792, 59.3604)
  line L15 (3.1868, 56.9208) -> (0.5833, 62.4199)
  circle C1 centre (0, 78.3527) radius 10.4204
  circle C2 centre (0, 44.3421) radius 4.9721
  circle C3 centre (0, 34.4424) radius 3.302
  circle C4 centre (-0.0444, 55.3911) radius 3.575
  circle C5 centre (-2.6479, 60.8902) radius 3.575
  point P6 (0, 92.71)
  point P7 (0, 29.21)
  point P8 (0, 78.3527)
  point P9 (0, 44.3421)
  point P10 (0, 34.4424)
  point P11 (-15.875, 31.1404)
  point P12 (15.875, 31.1404)
  point P13 (-15.875, 39.37)
  point P14 (15.875, 39.37)
  point P15 (-15.875, 51.816)
  point P16 (15.875, 51.816)
  point P19 (-15.875, 88.773)
  point P20 (15.875, 88.773)
  point P23 (-6.223, 88.773)
  point P24 (-6.223, 51.816)
  point P26 (3.5306, 51.816)
  point P27 (-6.223, 64.4652)
  point P28 (3.5306, 64.4652)
  point P29 (-3.2757, 53.8613)
  point P30 (0.5833, 62.4199)
  point P31 (3.1868, 56.9208)
  point P32 (-5.8792, 59.3604)
  midpoint L4 P6
  midpoint L2 P7
  coincident L5 P8
  coincident L5 P9
  coincident L5 P10
  coincident L1 P11
  coincident L3 P12
  perpendicular L3 L6
  coincident L1 P13
  coincident L3 P14
  perpendicular L3 L7
  coincident L1 P15
  coincident L3 P16
  perpendicular L3 L8
  coincident L1 P19
  coincident L3 P20
  perpendicular L3 L10
  tangent C1 L10
  tangent C3 L6
  tangent C2 L7
  tangent L8 C4
  coincident L10 P23
  coincident L8 P24
  perpendicular L8 L11
  coincident L8 P26
  perpendicular L8 L12
  tangent C4 L12
  tangent C5 L11
  coincident L11 P27
  coincident L12 P28
  perpendicular L12 L13
  tangent C5 L13
  tangent C5 L15
  tangent C4 L15
  tangent C4 L14
  tangent C5 L14
  coincident C4 P29
  coincident C5 P30
  coincident C4 P31
  coincident C5 P32
  dimension "d279" diameter C1 = 20.8407
  dimension "d280" diameter C2 = 9.9441
  dimension "d281" diameter C3 = 6.604
  dimension "d282" distance L6 L9 = 1.9304
  dimension "d283" distance L7 L9 = 10.16
  dimension "d284" distance L8 L9 = 22.606
  dimension "d285" distance L4 L10 = 3.937
  dimension "d286" diameter C4 = 7.1501
  dimension "d287" diameter C5 = 7.1501
  dimension "d289" distance P19 L11 = 9.652
  dimension "d290" distance L3 L12 = 12.3444
  dimension "d291" distance L4 L13 = 28.2448
extrude "Extrude7" cut sketch "Sketch6" profile of C1 C2 C3 C4 C5 L14 L15 against normal blind 27.94
base_feature "Base Feature1"
base_feature "Base Feature1"
remove_body "RemoveBody1"
remove_body "RemoveBody2"
remove_body "RemoveBody3"
copy_paste_bodies "CopyPasteBodies1"
move "Move1"
align "Align1"
position "Position6"
extrude "Extrude1" add of existing geometry blind 6.35
split "Split1"
remove_instance "RemoveInstance1"
position "Position7"
sketch "Sketch2" plane through (-15.875, 0, 0) normal (1, 0, 0) x axis (0, 1, 0)
  circle C1 centre (0, 38.1) radius 6.8407
  circle C2 centre (0, 38.1) radius 4.35
  circle C3 centre (0, 38.1) radius 4
  circle C4 centre (0, 38.1) radius 4
  circle C5 centre (0, 38.1) radius 7.8423
  circle C6 centre (0, 38.1) radius 14.3129
  concentric C3 C5
  concentric C3 C6
  dimension "d296" diameter C5 = 15.6845
  dimension "d297" diameter C6 = 28.6258
extrude "Extrude2" new body sketch "Sketch2" along normal blind 15.875 (= "( 1.25 / 2 ) * 1 in")
extrude "Extrude3" cut sketch "Sketch2" profile of C5 C6 along normal blind 0.6604
fillet "Fillet1" radius 12.7
work_plane "WorkPlane1" AlongDistance -16.51
sketch "Sketch3" plane through (1.2954, 0, 38.1) normal (-1, 0, 0) x axis (0, 1, 0)
  line L1 (0, -14.3129) -> (0, 0)
  circle C1 centre (0, 0) radius 14.3129
  circle C2 centre (0, 0) radius 4
  arc A1 centre (23.112, -10.5355) radius 25.4 clockwise from (-2.0269, -14.1687) to (0, 0)
  arc A2 centre (24.371, -7.1565) radius 25.4 clockwise from (0, -14.3129) to (0, 0)
  arc A3 centre (0, 0) radius 14.3129 clockwise from (0, -14.3129) to (-2.0269, -14.1687)
  arc A4 centre (25.0512, -4.1947) radius 25.4 clockwise from (1.7093, -14.2105) to (0, 0)
  arc A5 centre (25.3928, -0.6049) radius 25.4 clockwise from (3.7045, -13.8252) to (0, 0)
  arc A6 centre (0, 0) radius 14.3129 clockwise from (3.7045, -13.8252) to (1.7093, -14.2105)
  arc A7 centre (25.2833, 2.4319) radius 25.4 clockwise from (5.329, -13.2839) to (0, 0)
  arc A8 centre (24.6841, 5.9878) radius 25.4 clockwise from (7.1565, -12.3953) to (0, 0)
  arc A9 centre (0, 0) radius 14.3129 clockwise from (7.1565, -12.3953) to (5.329, -13.2839)
  arc A10 centre (23.7924, 8.8929) radius 25.4 clockwise from (8.5855, -11.452) to (0, 0)
  arc A11 centre (22.2933, 12.1725) radius 25.4 clockwise from (10.1207, -10.1207) to (0, 0)
  arc A12 centre (0, 0) radius 14.3129 clockwise from (10.1207, -10.1207) to (8.5855, -11.452)
  arc A13 centre (20.68, 14.7478) radius 25.4 clockwise from (11.257, -8.8397) to (0, 0)
  arc A14 centre (18.3832, 17.5277) radius 25.4 clockwise from (12.3953, -7.1564) to (0, 0)
  arc A15 centre (0, 0) radius 14.3129 clockwise from (12.3953, -7.1564) to (11.257, -8.8397)
  arc A16 centre (16.1584, 19.5976) radius 25.4 clockwise from (13.1613, -5.6249) to (0, 0)
  arc A17 centre (13.2203, 21.6883) radius 25.4 clockwise from (13.8252, -3.7045) to (0, 0)
  arc A18 centre (0, 0) radius 14.3129 clockwise from (13.8252, -3.7045) to (13.1613, -5.6249)
  arc A19 centre (10.5355, 23.112) radius 25.4 clockwise from (14.1687, -2.0269) to (0, 0)
  arc A20 centre (7.1565, 24.371) radius 25.4 clockwise from (14.3129, 0) to (0, 0)
  arc A21 centre (0, 0) radius 14.3129 clockwise from (14.3129, 0) to (14.1687, -2.0269)
  arc A22 centre (4.1947, 25.0512) radius 25.4 clockwise from (14.2105, 1.7093) to (0, 0)
  arc A23 centre (0.6049, 25.3928) radius 25.4 clockwise from (13.8252, 3.7045) to (0, 0)
  arc A24 centre (0, 0) radius 14.3129 clockwise from (13.8252, 3.7045) to (14.2105, 1.7093)
  arc A25 centre (-2.4319, 25.2833) radius 25.4 clockwise from (13.2839, 5.329) to (0, 0)
  arc A26 centre (-5.9878, 24.6841) radius 25.4 clockwise from (12.3953, 7.1565) to (0, 0)
  arc A27 centre (0, 0) radius 14.3129 clockwise from (12.3953, 7.1565) to (13.2839, 5.329)
  arc A28 centre (-8.8929, 23.7924) radius 25.4 clockwise from (11.452, 8.5855) to (0, 0)
  arc A29 centre (-12.1725, 22.2933) radius 25.4 clockwise from (10.1207, 10.1207) to (0, 0)
  arc A30 centre (0, 0) radius 14.3129 clockwise from (10.1207, 10.1207) to (11.452, 8.5855)
  arc A31 centre (-14.7478, 20.68) radius 25.4 clockwise from (8.8397, 11.257) to (0, 0)
  arc A32 centre (-17.5277, 18.3832) radius 25.4 clockwise from (7.1565, 12.3953) to (0, 0)
  arc A33 centre (0, 0) radius 14.3129 clockwise from (7.1565, 12.3953) to (8.8397, 11.257)
  arc A34 centre (-19.5976, 16.1584) radius 25.4 clockwise from (5.6249, 13.1613) to (0, 0)
  arc A35 centre (-21.6883, 13.2203) radius 25.4 clockwise from (3.7045, 13.8252) to (0, 0)
  arc A36 centre (0, 0) radius 14.3129 clockwise from (3.7045, 13.8252) to (5.6249, 13.1613)
  arc A37 centre (-23.112, 10.5355) radius 25.4 clockwise from (2.0269, 14.1687) to (0, 0)
  arc A38 centre (-24.371, 7.1565) radius 25.4 clockwise from (0, 14.3129) to (0, 0)
  arc A39 centre (0, 0) radius 14.3129 clockwise from (0, 14.3129) to (2.0269, 14.1687)
  arc A40 centre (-25.0512, 4.1947) radius 25.4 clockwise from (-1.7093, 14.2105) to (0, 0)
  arc A41 centre (-25.3928, 0.6049) radius 25.4 clockwise from (-3.7045, 13.8252) to (0, 0)
  arc A42 centre (0, 0) radius 14.3129 clockwise from (-3.7045, 13.8252) to (-1.7093, 14.2105)
  arc A43 centre (-25.2833, -2.4319) radius 25.4 clockwise from (-5.329, 13.2839) to (0, 0)
  arc A44 centre (-24.6841, -5.9878) radius 25.4 clockwise from (-7.1565, 12.3953) to (0, 0)
  arc A45 centre (0, 0) radius 14.3129 clockwise from (-7.1565, 12.3953) to (-5.329, 13.2839)
  arc A46 centre (-23.7924, -8.8929) radius 25.4 clockwise from (-8.5855, 11.452) to (0, 0)
  arc A47 centre (-22.2933, -12.1725) radius 25.4 clockwise from (-10.1207, 10.1207) to (0, 0)
  arc A48 centre (0, 0) radius 14.3129 clockwise from (-10.1207, 10.1207) to (-8.5855, 11.452)
  arc A49 centre (-20.68, -14.7478) radius 25.4 clockwise from (-11.257, 8.8397) to (0, 0)
  arc A50 centre (-18.3832, -17.5277) radius 25.4 clockwise from (-12.3953, 7.1565) to (0, 0)
  arc A51 centre (0, 0) radius 14.3129 clockwise from (-12.3953, 7.1565) to (-11.257, 8.8397)
  arc A52 centre (-16.1584, -19.5976) radius 25.4 clockwise from (-13.1613, 5.6249) to (0, 0)
  arc A53 centre (-13.2203, -21.6883) radius 25.4 clockwise from (-13.8252, 3.7045) to (0, 0)
  arc A54 centre (0, 0) radius 14.3129 clockwise from (-13.8252, 3.7045) to (-13.1613, 5.6249)
  arc A55 centre (-10.5355, -23.112) radius 25.4 clockwise from (-14.1687, 2.0269) to (0, 0)
  arc A56 centre (-7.1565, -24.371) radius 25.4 clockwise from (-14.3129, 0) to (0, 0)
  arc A57 centre (0, 0) radius 14.3129 clockwise from (-14.3129, 0) to (-14.1687, 2.0269)
  arc A58 centre (-4.1947, -25.0512) radius 25.4 clockwise from (-14.2105, -1.7093) to (0, 0)
  arc A59 centre (-0.6049, -25.3928) radius 25.4 clockwise from (-13.8252, -3.7045) to (0, 0)
  arc A60 centre (0, 0) radius 14.3129 clockwise from (-13.8252, -3.7045) to (-14.2105, -1.7093)
  arc A61 centre (2.4319, -25.2833) radius 25.4 clockwise from (-13.2839, -5.329) to (0, 0)
  arc A62 centre (5.9878, -24.6841) radius 25.4 clockwise from (-12.3953, -7.1564) to (0, 0)
  arc A63 centre (0, 0) radius 14.3129 clockwise from (-12.3953, -7.1564) to (-13.2839, -5.329)
  arc A64 centre (8.8929, -23.7924) radius 25.4 clockwise from (-11.452, -8.5855) to (0, 0)
  arc A65 centre (12.1725, -22.2933) radius 25.4 clockwise from (-10.1207, -10.1207) to (0, 0)
  arc A66 centre (0, 0) radius 14.3129 clockwise from (-10.1207, -10.1207) to (-11.452, -8.5855)
  arc A67 centre (14.7478, -20.68) radius 25.4 clockwise from (-8.8397, -11.257) to (0, 0)
  arc A68 centre (17.5277, -18.3832) radius 25.4 clockwise from (-7.1565, -12.3953) to (0, 0)
  arc A69 centre (0, 0) radius 14.3129 clockwise from (-7.1565, -12.3953) to (-8.8397, -11.257)
  arc A70 centre (19.5976, -16.1584) radius 25.4 clockwise from (-5.6249, -13.1613) to (0, 0)
  arc A71 centre (21.6883, -13.2203) radius 25.4 clockwise from (-3.7045, -13.8252) to (0, 0)
  arc A72 centre (0, 0) radius 14.3129 clockwise from (-3.7045, -13.8252) to (-5.6249, -13.1613)
  point P4 (-2.0269, -14.1687)
  point P2 (0, 0)
  point P3 (0, 0)
  point P7 (0, -14.3129)
  point P6 (0, 0)
  point P9 (0, 0)
  point P10 (0, -14.3129)
  coincident C1 P4
  coincident P2 P3
  coincident C1 P7
  coincident P2 P6
  coincident P2 P9
  coincident C1 P10
  vertical L1
  coincident P7 P10
  dimension "d305" distance P4 P7 = 2.032
  dimension "d306" radius A2 = 25.4
  dimension "d307" radius A1 = 25.4
  dimension "d308" radius A3 = 14.3129
  dimension "d310" C-Pattern1-Angle = 360
extrude "Extrude4" add sketch "Sketch3" profile of C2 A1 A2 A3 A4 A5 A6 A7 A8 A9 A10 A11 A12 A13 A14 A15 A16 A17 A18 A19 A20 A21 A22 A23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 along normal blind 16.51
extrude "Extrude5" cut of existing geometry blind -16.51
extrude "Extrude6" cut of existing geometry to an object
sketch "Sketch4" plane through (-15.875, 0, 0) normal (-1, 0, 0) x axis (0, -1, 0)
  circle C1 centre (0, 38.1) radius 7.8423
  circle C2 centre (0, 38.1) radius 4
  circle C3 centre (0, 38.1) radius 14.224
  concentric C1 C3
  dimension "d317" diameter C3 = 28.448
extrude "Extrude7" new body sketch "Sketch4" profile of C1 C3 against normal blind 15.748
delete_face "DeleteFace1"
fillet "Fillet2" radius 13.208
extrude "Extrude8" cut of existing geometry to an object
combine "Combine1"
extrude "Extrude9" new body of existing geometry blind -77.4954
combine "Combine2"
mirror "Mirror1" mirrorStitchTolerance 0.1016
fillet "Fillet3" radius 0.635
fillet "Fillet4" radius 0.254
sketch "Sketch5" plane through (53.6875, 0, 0) normal (1, 0, 0) x axis (0, 1, 0)
  line L1 (2.3812, 41.314) -> (-2.3813, 41.314)
  line L2 (-3.974, 38.5552) -> (-1.5928, 34.4308)
  line L3 (1.5928, 34.4308) -> (3.974, 38.5552)
  circle C1 centre (0, 38.1) radius 4
  point P3 (-2.3813, 41.314)
  point P4 (2.3812, 41.314)
  coincident C1 P3
  coincident C1 P4
  horizontal L1
  dimension "d332" distance P3 P4 = 4.7625 (= "( 3 / 16 ) * 1 in")
  dimension "d334" C-Pattern1-Angle = 360
extrude "Extrude10" cut sketch "Sketch5" against normal blind 25.4
fillet "Fillet5" radius 1.27
base_feature "Base Feature1"
position "Position8"
copy_paste "CutPaste1"
copy_paste "CutPaste2"
copy_paste "CutPaste3"
copy_paste "CutPaste4"
copy_paste "CutPaste1"
sketch "Sketch7" plane through (0, -35.687, 0) normal (0, -1, 0) x axis (1, 0, 0)
  line L1 (-5.8792, 59.3604) -> (-3.2757, 53.8613)
  line L2 (3.1868, 56.9208) -> (0.5833, 62.4199)
  line L3 (-15.875, 29.21) -> (-15.875, 92.71)
  line L4 (15.875, 29.21) -> (-15.875, 29.21)
  line L5 (15.875, 92.71) -> (15.875, 29.21)
  line L6 (-15.875, 92.71) -> (15.875, 92.71)
  line L7 (11.43, 29.21) -> (-11.43, 29.21)
  line L8 (11.43, 41.1163) -> (11.43, 29.21)
  line L9 (15.875, 41.1163) -> (11.43, 41.1163)
  line L10 (0, 34.4424) -> (0, 29.21)
  line L11 (-11.43, 41.1163) -> (-11.43, 29.21)
  line L12 (-15.875, 41.1163) -> (-11.43, 41.1163)
  circle C1 centre (0, 44.3421) radius 4.9721
  circle C2 centre (0, 34.4424) radius 3.302
  arc A1 centre (-0.0444, 55.3911) radius 3.5751 clockwise from (3.1868, 56.9208) to (-3.2757, 53.8613)
  arc A2 centre (-2.6479, 60.8902) radius 3.575 clockwise from (-5.8792, 59.3604) to (0.5833, 62.4199)
  circle C3 centre (0, 78.3527) radius 10.4204
  point P15 (-11.43, 29.21)
  point P18 (15.875, 41.1163)
  point P19 (0, 29.21)
  point P3 (0, 34.4424)
  point P20 (0, 34.4424)
  point P16 (11.43, 29.21)
  point P21 (-11.43, 29.21)
  point P17 (11.43, 41.1163)
  point P22 (-11.43, 41.1163)
  point P23 (-15.875, 41.1163)
  coincident L4 P15
  midpoint L4 L7
  perpendicular L4 L8
  coincident L5 P18
  perpendicular L5 L9
  midpoint L4 P19
  coincident P3 P20
  symmetric P16 L10 P21
  symmetric P17 L10 P22
  symmetric P18 L10 P23
  dimension "d339" distance P15 P16 = 22.86
  dimension "d340" distance P16 P17 = 11.9062 (= "( 15 / 32 ) * 1 in")
extrude "Extrude8" cut sketch "Sketch7" profile of L3 L4 L5 L8 L9 L11 L12 against normal blind 30.48
fillet "Fillet2" radius 2.54
chamfer "Chamfer1" distance 0.254 Rotate Angle 85
sketch "Sketch3" plane through (0, 0, -12.7) normal (0, 0, -1) x axis (1, 0, 0)
  line L1 (30.1625, -74.8109) -> (-30.1625, -74.8109)
  line L2 (38.1, 66.8734) -> (38.1, -66.8734)
  line L3 (-30.1625, 74.8109) -> (30.1625, 74.8109)
  line L4 (-38.1, -66.8734) -> (-38.1, 66.8734)
  line L5 (12.7, 0.6112) -> (12.7, 32.7422)
  line L6 (-7.9375, -4.1513) -> (7.9375, -4.1513)
  line L7 (-12.7, 32.7422) -> (-12.7, 0.6112)
  line L8 (7.9375, 37.5047) -> (-7.9375, 37.5047)
  line L9 (38.1, 0) -> (-38.1, 0)
  line L10 (0, 74.8109) -> (0, 0)
  line L11 (0, 72.9059) -> (0, 74.8109)
  circle C1 centre (22.225, -25.4) radius 5.1594
  circle C2 centre (22.225, 25.4) radius 5.1594
  circle C3 centre (-22.225, -25.4) radius 5.1594
  circle C4 centre (-22.225, 25.4) radius 5.1594
  circle C5 centre (0, -14.8669) radius 5.1594
  arc A1 centre (-30.1625, -66.8734) radius 7.9375 clockwise from (-30.1625, -74.8109) to (-38.1, -66.8734)
  arc A2 centre (30.1625, -66.8734) radius 7.9375 clockwise from (38.1, -66.8734) to (30.1625, -74.8109)
  arc A3 centre (30.1625, 66.8734) radius 7.9375 clockwise from (30.1625, 74.8109) to (38.1, 66.8734)
  arc A4 centre (-30.1625, 66.8734) radius 7.9375 clockwise from (-38.1, 66.8734) to (-30.1625, 74.8109)
  circle C6 centre (28.575, 65.2859) radius 3.9687
  circle C7 centre (-28.575, 65.2859) radius 3.9687
  circle C8 centre (0, -62.4919) radius 3.9687
  arc A5 centre (7.9375, 0.6112) radius 4.7625 clockwise from (12.7, 0.6112) to (7.9375, -4.1513)
  arc A6 centre (-7.9375, 0.6112) radius 4.7625 clockwise from (-7.9375, -4.1513) to (-12.7, 0.6112)
  arc A7 centre (-7.9375, 32.7422) radius 4.7625 clockwise from (-12.7, 32.7422) to (-7.9375, 37.5047)
  arc A8 centre (7.9375, 32.7422) radius 4.7625 clockwise from (7.9375, 37.5047) to (12.7, 32.7422)
  circle C9 centre (30.1625, 66.8734) radius 7.9375
  circle C10 centre (-30.1625, 66.8734) radius 7.9375
  arc A9 centre (0, 304.7074) radius 231.8015 clockwise from (29.1639, 74.7479) to (-29.1639, 74.7479)
  circle C11 centre (30.1625, -66.8734) radius 7.9375
  arc A10 centre (0, -304.7074) radius 231.8015 clockwise from (-29.1639, -74.7479) to (29.1639, -74.7479)
  circle C12 centre (-30.1625, -66.8734) radius 7.9375
  point P36 (-38.1, 0)
  point P37 (38.1, 0)
  point P1 (0, 0)
  point P39 (0, 0)
  point P40 (0, 74.8109)
  point P41 (-29.1639, 74.7479)
  point P42 (29.1639, 74.7479)
  point P43 (0, 72.9059)
  point P46 (-29.1639, -74.7479)
  point P47 (29.1639, -74.7479)
  tangent A3 C9
  tangent A4 C10
  midpoint L4 P36
  midpoint L2 P37
  tangent C9 A9
  tangent C10 A9
  coincident P1 P39
  midpoint L3 P40
  coincident C10 P41
  coincident C9 P42
  perpendicular L3 L11
  coincident A9 P43
  symmetric C9 L9 C11
  symmetric C10 L9 C12
  symmetric L9 A9 A10
  symmetric L9 P41 P46
  symmetric L9 P42 P47
  dimension "d347" diameter C9 = 15.875
  dimension "d348" diameter C10 = 15.875
  dimension "d349" distance P40 P43 = 1.905
work_plane "WorkPlane1" AlongDistance 0
extrude "Extrude6" cut sketch "Sketch3" profile of L1 L3 C9 C10 A9 C11 A10 C12 against normal blind 12.7
sketch "Sketch4" plane through (0, -74.8109, -6.35) normal (0, -1, 0) x axis (1, 0, 0)
  line L1 (29.1639, -6.35) -> (-29.1639, -6.35)
  line L2 (-29.1639, 6.35) -> (29.1639, 6.35)
  line L3 (-29.1639, -6.35) -> (-38.1, -6.35)
  line L4 (38.1, -6.35) -> (29.1639, -6.35)
  line L5 (-38.1, 6.35) -> (-38.1, -6.35)
  line L6 (-38.1, 6.35) -> (-29.1639, 6.35)
  line L7 (38.1, 6.35) -> (29.1639, 6.35)
  line L8 (38.1, -6.35) -> (38.1, 6.35)
  curve K1
  curve K2
  curve K3
  curve K4
  line L9 (0, -6.35) -> (0, 6.35)
  line L10 (-25.4, 3.175) -> (25.4, 3.175)
  line L11 (-25.4, -3.175) -> (-25.4, 3.175)
  line L12 (25.4, -3.175) -> (-25.4, -3.175)
  line L13 (25.4, 3.175) -> (25.4, -3.175)
  line L14 (-25.4, -3.175) -> (25.4, 3.175)
  line L15 (25.4, -3.175) -> (-25.4, 3.175)
  curve K5
  curve K6
  curve K7
  curve K8
  point P10 (0, 6.35)
  point P11 (0, -6.35)
  point P16 (0, 0)
  point P1 (0, 0)
  point P14 (-25.4, -3.175)
  point P15 (25.4, -3.175)
  point P13 (-25.4, 3.175)
  midpoint L2 P10
  midpoint L1 P11
  horizontal L10
  perpendicular L10 L11
  parallel L10 L12
  parallel L11 L13
  coincident L14 P16
  coincident L15 P16
  coincident P1 P16
  collinear K2 L13
  collinear K1 L12
  collinear K3 L10
  coincident K1
  dimension "d356" distance K2 K4 = 50.8
  dimension "d357" distance P14 P15 = 50.8
  dimension "d358" distance P13 P14 = 6.35
  dimension "d355" Text1-Height = 5.588
  dimension "d359" Text2-Height = 2.3813
emboss "Emboss1" sketch "Sketch4" Depth -0.25 Horizontal Distance 0 Vertical Distance 0 Rotation Angle 0
fillet "Fillet3" radius 1.27
fillet "Fillet4" radius 1.27
work_plane "WorkPlane2" AlongDistance -19.05
split "Split1" bodies "Knob (1)"
remove_body "RemoveBody1"
extrude "Extrude13" cut of existing geometry blind -0.254 taper -70
extrude "Extrude14" add of existing geometry blind 0.254
fillet "Fillet5" radius 10.541
fillet "Fillet1" radius 0.0254
fillet "Fillet3" radius 0.0254
fillet "Fillet3" radius 0.0254
fillet "Fillet6" radius 1.27
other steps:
base_feature "Base Feature1"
